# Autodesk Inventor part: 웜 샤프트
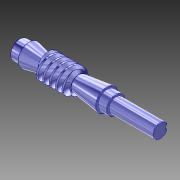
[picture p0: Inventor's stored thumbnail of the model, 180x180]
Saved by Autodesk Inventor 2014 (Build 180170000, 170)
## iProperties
Created: 2013-01
Part Number: 웜 샤프트
Material: 탄소강
Document SubType Name: Modeling
Designer: 한국산업디자인학원[gmhk.co.kr]
Categories: <?xml version="1.0" encoding="UTF-16"?> <MemberInstance><Categories><FamilyTemplate><FamilyTemplateParameter ValueType="xs:double" Id="1" ObjectReferenceKey="da
Density: 7.87 g/cm^3
Mass: 4103.46 g
Surface Area: 646.883 cm^2
Volume: 521.405 cm^3
Appearance: _시험-파란색 크롬
CustomPartVersion: 1
Author: 한국산업디자인학원[gmhk.co.kr]
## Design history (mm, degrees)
body "Solid1"
extrude "기본 본체" new body stored distance "d6" = 80 (= da_b); taper "d7" = 0 deg
chamfer "Chamfer1" distance "d8" = 4.00367 (= fd_cham1); stored, may be unused: second distance "d9" = 11 (= 0.5 x fd_cham2), angle "d47" = 45 deg
chamfer "Chamfer2" distance "d10" = 4.00367 (= fd_cham1); stored, may be unused: second distance "d11" = 11 (= 0.5 x fd_cham2), angle "d48" = 45 deg
sketch "톱니 스케치"
  geometry: L1 (0, 21.74)-(0, 10.96) reference; L2 (-60.834, 30.3)-(-56.721, 19); L3 (-53.235, 19)-(-49.122, 30.3); L4 (-50.535, 0)-(-37.455, 0) reference; L5 (-60.834, 30.3)-(-54.978, 30.3); L6 (-54.978, 30.3)-(-49.122, 30.3); L7 (-56.721, 19)-(-54.978, 19); L8 (-54.978, 19)-(-53.235, 19); L9 (-54.978, 25)-(-51.051, 25); L10 (-54.978, 30.3)-(-54.978, 19)
  constraints: 16 end point, 3 equal length, 3 parallel, 2 collinear, 2 point on line
  dimensions: "d24" = 110 deg angle of L7 L2 (computed from da_alfat); "d25" = 54.97787 distance from line of L1 L5.end (= fd_dist); "d26" = 3.92699 distance of L9.start L9.end (= 0.25 x da_px); "d27" = 19 distance between parallel lines of L4 L7 (= 0.5 x da_df); "d28" = 25 distance between parallel lines of L4 L9 (= 0.5 x da_d); "d29" = 30.3 distance between parallel lines of L4 L5 (= 0.505 x da_da)
feature "톱니" pitch "d30" = 31.41593 (computed from da_px, da_z); turns "d32" = 8 (= fd_n); dims "d31" = 10, "d33" = 0, angle "d34" = 90 deg, angle "d35" = 90 deg, "d36" = 0, "d37" = 0, "d70" = 10, "da_rightdir" = 0 [user parameter]
pattern_circular "톱니 패턴" dims angle "d46" = 360 deg, "da_rightdir" = 0 [user parameter]
feature "왼쪽 톱니" pitch "d62" = 31.41593 (computed from da_px, da_z); turns "d64" = 8 (= fd_n); dims "d63" = 10, "d65" = 0, angle "d66" = 90 deg, angle "d67" = 90 deg, "d68" = 0, "d69" = 0, "d76" = 10, "da_rightdir" = 0 [user parameter]
pattern_circular "왼쪽 톱니 패턴" dims angle "d73" = 360 deg, "da_rightdir" = 0 [user parameter]
sketch "스케치8"
  geometry: C1 r 18.99 at (0, 0); A1 r 19 centre (0, 0) between (9.02, 16.723) and (-3.823, 18.611) reference; A2 r 19 centre (0, 0) between (-3.823, 18.611) and (-9.02, -16.723) reference; A3 r 19 centre (0, 0) between (-9.02, -16.723) and (3.823, -18.611) reference; A4 r 19 centre (0, 0) between (3.823, -18.611) and (9.02, 16.723) reference; 1 further point
  constraints: 1 centre point, 1 coincident
  dimensions: "d87" = 0.01 radial gap between concentric circles of C1 A2
node "작업 평면10"
extrude "돌출2" join sketch "스케치8" distance "d88" = 1; taper "d89" = 0 deg
mirror "대칭1"
revolve "회전1" stored, may be unused: angle "d90" = 90 deg
chamfer "모따기3" distance "d91" = 1; stored, may be unused: second distance "d92" = 2, angle "d93" = 45 deg
node "작업 평면11"
sketch "스케치9"
  geometry: L1 (-54.5, -16.5)-(-54.5, 16.5) reference; L2 (-54.5, 5)-(-23.5, 5); L3 (-23.5, -5)-(-54.5, -5); A1 r 5 centre (-23.5, 0) between (-23.5, -5) and (-23.5, 5); 2 further points
  constraints: 4 end point, 2 perpendicular, 2 point on circle, 2 point on line, 2 tangent, 1 centre point, 1 horizontal alignment, 1 midpoint
  dimensions: "d94" = 10 distance between parallel lines of L3 L2; "d96" = 36 dimension on A1 L1
extrude "돌출3" cut sketch "스케치9" distance "d97" = 5; taper "d98" = 0 deg
node "기본 본체 스케치" dims "d5" = 60 (= da_da)
sketch "Sketch5"
  geometry: C1 r 30 at (0, 0) reference; C2 r 25 at (0, 0)
  constraints: 1 centre point, 1 coincident
  dimensions: "d59" = 50 diameter of C2 (= da_d)
body "Srf1"
sketch "스케치7"
  geometry: L1 (40, 18.611)-(40, -16.723) reference; L2 (40, 19)-(40, 16.723) reference; L3 (40, 18.611)-(40, 16.723) reference; L4 (40, -16.723)-(40, 18.611) reference; L5 (40, -18.611)-(40, -16.723) reference; L6 (40, 16.723)-(40, -18.611) reference; L7 (40, -16.723)-(40, -19) reference; L8 (41, 0)-(241, 0); L9 (110, 27.5)-(110, 22.5); L10 (110, 22.5)-(132, 22.5); L11 (132, 22.5)-(132, 17.5); L12 (132, 17.5)-(241, 17.5); L13 (241, 17.5)-(241, 0); L14 (127.9, 22.5)-(111.1, 22.5) reference; L15 (110, -41.4)-(110, 41.4) reference; L16 (-40, -16.723)-(-40, 18.611) reference; L17 (-41, 0)-(-105, 0); L18 (25.305, 19)-(-40, 19) reference; L19 (-82, 27.5)-(-82, 22.5); L20 (-82, 22.5)-(-105, 22.5); L21 (-105, 22.5)-(-105, 0); L22 (-82, 41.4)-(-82, -41.4) reference; L23 (41, 18.99)-(41, -18.99) reference; L24 (41, 0)-(41, 18.99); L25 (41, 18.99)-(110, 27.5); L26 (-41, 18.99)-(-41, -18.99) reference; L27 (-41, 0)-(-41, 18.99); L28 (-41, 18.99)-(-82, 27.5); 1 further point
  constraints: 30 end point, 7 collinear, 7 perpendicular, 2 midpoint, 1 horizontal, 1 horizontal alignment, 1 parallel, 1 point on line, 2 other
  dimensions: "d82" = 35 diameter of L12 L8; "d83" = 55 diameter of L9.start L8; "d84" = 22 distance of L9.end L10.end; "d85" = 200 distance of L8.start L8.end; "d86" = 64 distance of L17.start L17.end
node "투영된 루프1"
node "참조1"
node "참조2"
node "투영된 루프2"
feature "피치 지름" dims "d60" = 10, "d61" = 0
other parameters: "da_b" = 80 [user parameter; used in 3 equation terms], "da_df" = 38 [user parameter; used in 2 equation terms], "fd_cham2" = 22 (= da_da - da_df) [user parameter; used in 3 equation terms], "fd_cham1" = 4.00367 (= 0.181985 x fd_cham2) [user parameter; used in 2 equation terms], "da_d" = 50 [user parameter; used in 2 equation terms], "da_px" = 90 deg [user parameter; used in 5 equation terms], "fd_dist" = 54.97787 (computed from da_b, da_px) [user parameter; used in 1 equation term], "fd_n" = 8 (computed from da_b, da_px) [user parameter; used in 2 equation terms], "da_alfat" = 20 deg [user parameter; used in 1 equation term], "d12" = 110 deg (derived), "d14" = 3.1425 (derived), "d50" = 0, "d54" = 0, "d56" = 0, "d77" = 0, "d80" = 0
